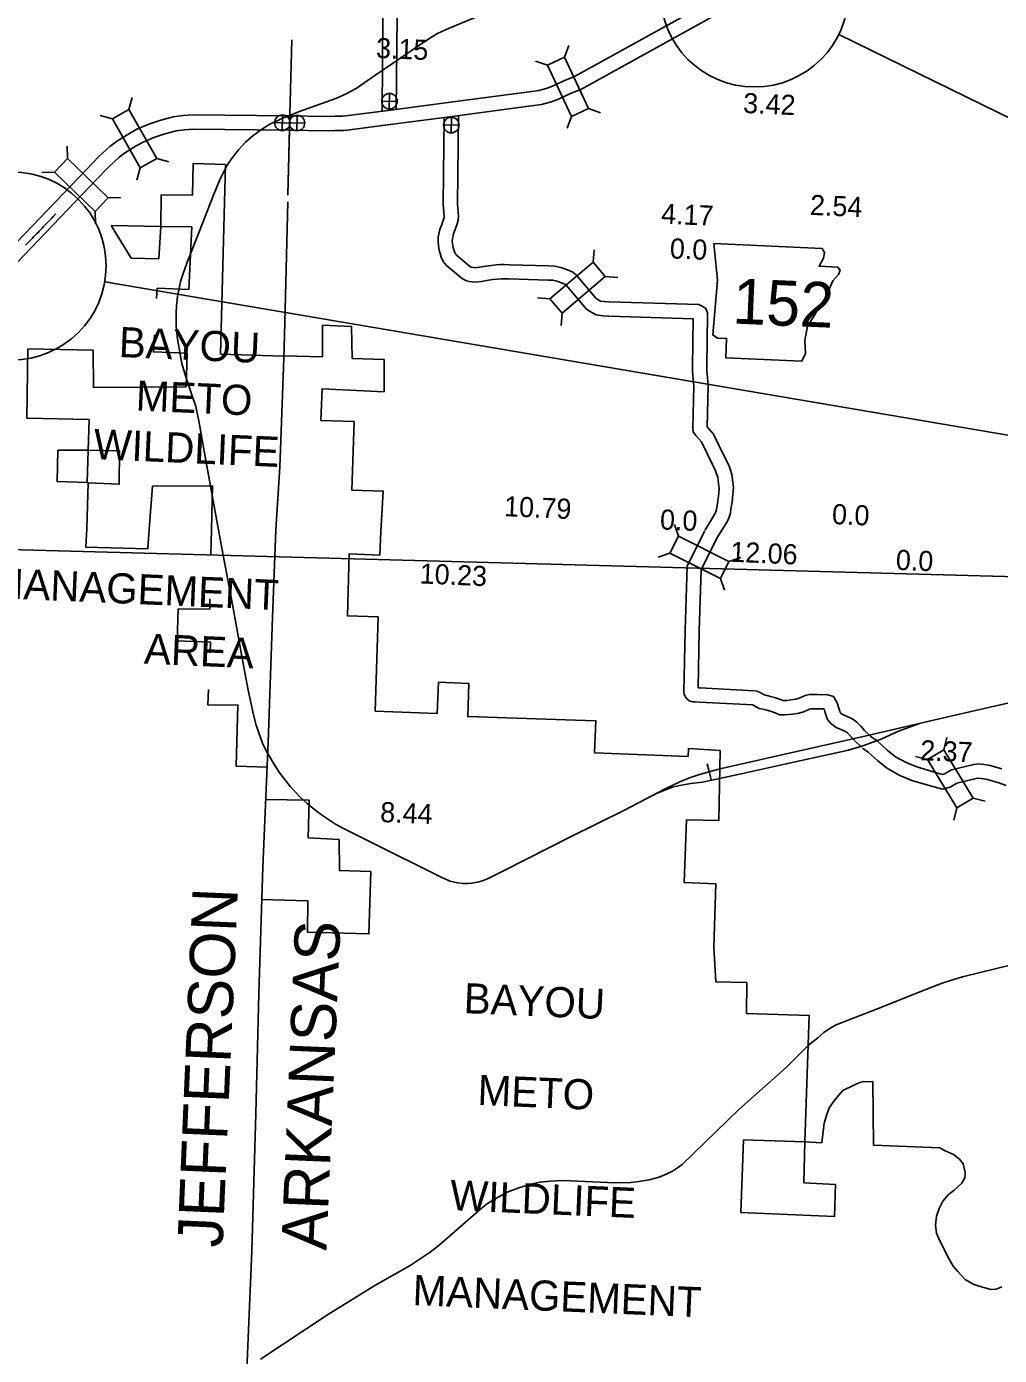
# Model space of a CAD drawing. Extents: x 1196286 to 1268366, y 2040822 to 2082115.
# Drawn here: x 1200093 to 1204184, y 2071244 to 2076830 of the extents above; entities that cross this region are included whole.
import ezdxf

# ---------------------------------------------------------------- set-up
doc = ezdxf.new("R2010")
doc.units = 0
for name, color, linetype in [('10', 7, 'Continuous'), ('55', 7, 'Continuous'), ('Level 100', 7, 'Continuous'), ('Level 70', 7, 'Continuous'), ('Level 78', 7, 'Continuous'), ('Level 8', 7, 'Continuous'), ('Level 82', 7, 'Continuous'), ('Level 84', 7, 'Continuous'), ('Level 87', 7, 'Continuous'), ('Level 95', 7, 'Continuous'), ('Level 96', 7, 'Continuous'), ('Level 97', 7, 'Continuous'), ('Level 98', 7, 'Continuous')]:
    doc.layers.add(name, color=color, linetype=linetype)

msp = doc.modelspace()

# ---------------------------------------------------------------- linework, layer by layer
at = {"layer": '10'}
for q in [(1202955.4, 2073731.2), (1202972, 2073665.2)]:
    msp.add_line((1202963.7, 2073698.2), q, dxfattribs=at)
for points in [[(1202150.4, 2076940.5), (1202116.4, 2076923.6), (1202008.7, 2076880), (1201857.3, 2076817.3), (1201821, 2076800.8), (1201785.3, 2076778.5), (1201558.1, 2076623.9), (1201479.7, 2076569.9), (1201437.3, 2076546.6), (1201393.2, 2076527.1), (1201236, 2076471.6), (1201170.7, 2076445.2), (1201116.4, 2076419.2), (1201080.8, 2076396.6)], [(1201080.8, 2076396.6), (1201044.5, 2076371), (1201013.9, 2076343.4), (1200984.8, 2076311.7), (1200954.9, 2076273.3), (1200937.3, 2076247.7), (1200922.1, 2076220.1), (1200904.1, 2076183.4), (1200878.9, 2076121.3), (1200806.6, 2075934.9), (1200771, 2075846.6), (1200752.7, 2075796.1), (1200741.2, 2075758.6), (1200734.3, 2075729), (1200728.6, 2075695), (1200724.4, 2075655.6), (1200722.1, 2075623.4), (1200722.5, 2075570.9), (1200727.8, 2075515.8), (1200746.2, 2075413.1), (1200761.9, 2075362.2), (1200788.6, 2075281.4), (1200805.1, 2075232.5), (1200818.1, 2075172), (1200836, 2075069.1), (1200875.4, 2074851.4), (1200919, 2074615.4), (1200959.6, 2074400.4), (1201000.5, 2074174.7), (1201025.7, 2074040.4), (1201047.1, 2073936.8), (1201058.8, 2073893.2), (1201069.5, 2073860.3), (1201086, 2073818.2), (1201101.3, 2073784.9), (1201139.5, 2073719.9), (1201157.9, 2073691.9), (1201203, 2073634.5), (1201243.9, 2073591.2), (1201274.9, 2073562.5), (1201310.8, 2073533.1), (1201337.6, 2073513.2), (1201362.8, 2073496.7), (1201391.9, 2073477.6), (1201428.2, 2073457), (1201540.6, 2073401.1), (1201839.2, 2073252.3), (1201874.8, 2073237.4), (1201905.7, 2073230.5), (1201926.4, 2073227.8), (1201948.2, 2073227.8), (1201966.1, 2073229), (1201988.7, 2073233.2), (1202010.5, 2073239.3), (1202034.6, 2073248.8), (1202100.7, 2073282.9), (1202380.6, 2073424.4), (1202607.7, 2073535.8), (1202780.9, 2073627.6), (1202840.6, 2073654.7), (1202880.7, 2073671.2), (1202913.6, 2073683.1), (1202961.4, 2073697.6), (1203014.9, 2073711), (1203325.4, 2073781.4), (1203635.9, 2073851.4), (1203870.2, 2073905.3), (1204137.1, 2073967.3), (1204305.7, 2074005.9)], [(1203846.9, 2073899.9), (1203759.2, 2073867.5), (1203688.6, 2073836.2), (1203614, 2073807.3), (1203548.9, 2073788.8), (1203286.4, 2073730.1), (1203098.5, 2073688.4), (1202987.7, 2073664.3), (1202935.5, 2073653.8), (1202886.6, 2073648.2), (1202839.2, 2073640.2), (1202809.5, 2073632.1), (1202738.3, 2073605)], [(1204451.5, 2072939), (1204028.9, 2072835.7), (1203977.5, 2072820), (1203943.1, 2072808.1), (1203906.2, 2072794.3), (1203834.8, 2072766.7), (1203692.1, 2072709.1), (1203497.4, 2072633.3), (1203471.7, 2072619.5), (1203445.4, 2072601.4), (1203419.7, 2072579.4), (1203381.5, 2072547.5), (1203286.4, 2072453.5), (1203088.5, 2072278.1), (1202849.4, 2072047), (1202830.6, 2072032), (1202808.7, 2072018.2), (1202783, 2072005.7), (1202753, 2071993.1), (1202711, 2071981.9), (1202667.8, 2071974.3), (1202634, 2071971.2), (1202567, 2071969.3), (1202349.2, 2071978.7), (1202295.3, 2071976.8), (1202250.9, 2071972.5), (1202215.2, 2071964.3), (1202162.6, 2071948.7), (1202114.4, 2071930.5), (1202075.6, 2071909.2), (1202031.1, 2071882.3), (1202003, 2071859.7), (1201827.7, 2071707.5), (1201790.1, 2071678), (1201705.6, 2071622.3), (1201557.8, 2071537.7), (1201362.5, 2071416.8), (1201077, 2071227.7)]]:
    msp.add_lwpolyline(points, dxfattribs=at)
at = {"layer": '55'}
for points in [[(1201208.7, 2076773.7), (1201199.8, 2076460.4), (1201191.6, 2076120.9)], [(1201208.7, 2076773.7), (1201199.8, 2076460.4), (1201199.7, 2076456)], [(1201198.2, 2076394.8), (1201191.6, 2076120.9)], [(1201191.4, 2076092.7), (1201179.2, 2075584), (1201175.2, 2075434.1), (1201158.1, 2074977.4), (1201141.4, 2074714.5)], [(1201191.4, 2076092.7), (1201179.2, 2075584), (1201175.2, 2075434.1), (1201158.1, 2074977.4), (1201141.4, 2074714.5)], [(1200995.4, 2070159.5), (1201003.9, 2070617.1), (1201018, 2071150.3), (1201039.9, 2071682.9), (1201057.3, 2072260.8), (1201069.7, 2072763.6), (1201086.6, 2073295.8), (1201108.5, 2073820.9), (1201126.8, 2074347), (1201141.4, 2074714.5)], [(1200995.4, 2070159.5), (1201003.9, 2070617.1), (1201018, 2071150.3), (1201039.9, 2071682.9), (1201057.3, 2072260.8), (1201069.7, 2072763.6), (1201086.6, 2073295.8), (1201108.5, 2073820.9), (1201126.8, 2074347), (1201141.4, 2074714.5)]]:
    msp.add_lwpolyline(points, dxfattribs=at)
at = {"layer": 'Level 100'}
for p, q in [((1201618.5, 2076483.4), (1201619.8, 2076548.5)), ((1201586.6, 2076516.6), (1201651.7, 2076515.3)), ((1201167.4, 2076392.9), (1201169.6, 2076457.9)), ((1201229.8, 2076391.9), (1201231.1, 2076457)), ((1201878.4, 2076383.2), (1201879.7, 2076448.3)), ((1201201, 2076424.3), (1201136, 2076426.5)), ((1201197.9, 2076425.1), (1201263, 2076423.8)), ((1201846.5, 2076416.4), (1201911.6, 2076415.1))]:
    msp.add_line(p, q, dxfattribs=at)
for centre, radius in [((1201619.1, 2076516), 32.6), ((1201168.5, 2076425.4), 32.5), ((1201230.5, 2076424.4), 32.6), ((1201879, 2076415.7), 32.6)]:
    msp.add_circle(centre, radius, dxfattribs=at)
at = {"layer": 'Level 70'}
for points in [[(1201171.9, 2075444.9), (1200909, 2075453.3), (1200929.5, 2076250), (1200794.2, 2076253.8), (1200791.4, 2076121.8), (1200659.9, 2076123.1), (1200657.5, 2075989.7), (1200649, 2075854.1), (1200533.5, 2075856.8), (1200449.6, 2075994.1)], [(1200449.6, 2075994.1), (1200657.5, 2075989.7), (1200787.8, 2075987.4), (1200775.3, 2075724.9), (1200642.5, 2075730.2), (1200640, 2075687.4)], [(1201582.5, 2074708), (1201593, 2074877), (1201460.4, 2074881.3), (1201471.2, 2075169.2), (1201331, 2075174.4), (1201335.9, 2075307.7), (1201596.4, 2075294.6), (1201596.3, 2075430.7), (1201462.7, 2075435.2), (1201459.2, 2075569.4), (1201338.2, 2075575.3), (1201337.5, 2075440.9), (1201173.8, 2075445.3)], [(1200631, 2075533.4), (1200626.9, 2075462.2), (1200768.3, 2075456.4), (1200764.1, 2075315.5), (1200375.1, 2075312.6), (1200373.8, 2075468.9), (1200099.3, 2075475), (1200093.9, 2075183.8), (1200356.5, 2075177.8), (1200352.8, 2075048.9), (1200225.4, 2075049.1), (1200221.4, 2074917), (1200347.6, 2074913.2), (1200352.3, 2074912.1), (1200346.3, 2074720.6)], [(1200347.6, 2074913.2), (1200352.8, 2075048.9)], [(1200352.8, 2075048.9), (1200484.3, 2075045.8), (1200483.1, 2074905.6), (1200352.3, 2074912.1)], [(1200609.4, 2074717.7), (1200623.3, 2074897.7), (1200874.7, 2074899.6), (1200870.3, 2074715.9)], [(1200609.4, 2074717.7), (1200602.8, 2074635), (1200342.2, 2074641.9), (1200346.3, 2074720.6)], [(1200870.3, 2074715.9), (1200868.1, 2074606.1)], [(1203361.2, 2071969.2), (1203364.8, 2072141.6), (1203383.9, 2072673.2), (1203120.1, 2072681.4), (1203121.2, 2072811), (1202991, 2072814.7), (1202983.5, 2072960.4), (1202990.7, 2073226.3), (1202858.4, 2073231.8), (1202867.4, 2073494.9), (1203003.8, 2073492.8), (1203009, 2073787.3), (1202875.9, 2073794.5), (1202874.7, 2073761.6), (1202481.2, 2073776.4), (1202486.8, 2073911.7), (1202359, 2073916.3), (1201948.2, 2073929), (1201952.8, 2074068), (1201825.6, 2074073.8), (1201819.6, 2073941.9), (1201559.7, 2073952.7), (1201571.9, 2074347.9), (1201442.7, 2074353.4), (1201449.2, 2074613.3), (1201578.8, 2074608.2), (1201582.5, 2074708)], [(1200864.5, 2074424.6), (1200863.6, 2074380.2), (1200731.2, 2074382), (1200727.1, 2074247.2), (1200866.7, 2074242.3), (1200864.9, 2074197.7)], [(1200858.4, 2074043.6), (1200855.7, 2073978.4), (1200982.2, 2073977.7), (1200974.7, 2073721.4), (1201106.5, 2073716.6)], [(1201080.1, 2073160.3), (1201275.3, 2073154.5), (1201274.3, 2073022.9), (1201532.7, 2073015.5), (1201540.5, 2073277.6), (1201408.5, 2073282.8), (1201407.5, 2073412.3), (1201277.9, 2073419.1), (1201280.9, 2073577.5), (1201096.4, 2073581.2)], [(1203364.8, 2072141.6), (1203436.7, 2072138.1), (1203443.2, 2072186.4), (1203446.2, 2072218.7), (1203455.2, 2072248), (1203467.7, 2072284.1), (1203491.3, 2072318.2), (1203525.8, 2072356.9), (1203569.4, 2072379), (1203597.2, 2072390.8), (1203613.6, 2072395.2)], [(1203613.6, 2072395.2), (1203627.5, 2072393.8), (1203652, 2072395.1), (1203653.9, 2072127.7), (1203932.8, 2072116.2), (1203949.5, 2072106.5), (1203967.9, 2072098.6), (1203990.8, 2072088.7), (1204015.4, 2072068.5), (1204030.8, 2072049.6), (1204040, 2072012.6), (1204038.6, 2071991), (1204024.9, 2071968.5), (1203992.5, 2071936.4), (1203969.4, 2071919.7), (1203945.6, 2071891.7), (1203930.8, 2071861.4), (1203919.6, 2071829.2), (1203914.7, 2071791.4), (1203918.8, 2071757.8), (1203933.3, 2071725), (1203948.8, 2071696.7), (1203964.8, 2071660.8), (1203989.4, 2071619.3), (1204008.7, 2071596.5), (1204040, 2071563.4), (1204072.7, 2071543.7), (1204098.1, 2071535.1), (1204148.1, 2071521.4), (1204170.2, 2071522.7), (1204194, 2071532.6)], [(1203364.8, 2072141.6), (1203107.8, 2072149.9), (1203095.8, 2071844.9), (1203490.5, 2071827.7), (1203494.4, 2071962.6), (1203361.2, 2071969.2)]]:
    msp.add_lwpolyline(points, dxfattribs=at)
at = {"layer": 'Level 78'}
msp.add_lwpolyline([(1202982.3, 2075917.3), (1202998.6, 2075764.2), (1202978.6, 2075533.9), (1202998.3, 2075520.4), (1203036.3, 2075518.7), (1203032.9, 2075437.6), (1203352.3, 2075423.9), (1203368.9, 2075456.2), (1203366.2, 2075509.7), (1203376.4, 2075570.2), (1203406.3, 2075617.2), (1203425.6, 2075651.9), (1203452.6, 2075688.9), (1203469.5, 2075728.8), (1203483.6, 2075761.2), (1203507.6, 2075788.1), (1203513.5, 2075805.6), (1203503.9, 2075818.8), (1203425.3, 2075822.1), (1203444.5, 2075856.9), (1203448, 2075879.6), (1203438.3, 2075897.5)], close=True, dxfattribs=at)
at = {"layer": 'Level 8'}
for p in [(1203508.5, 2076797.1), (1200422, 2075757.5), (1199280.2, 2074652.1)]:
    msp.add_line(p, (1208376.7, 2074405.8), dxfattribs=at)
msp.add_lwpolyline([(1200216.8, 2076042.6), (1200205.5, 2076031), (1200199.7, 2076025), (1200193.9, 2076019), (1200188, 2076013), (1200182.2, 2076007), (1200176.3, 2076001), (1200170.5, 2075995), (1200164.7, 2075989), (1200158.9, 2075983), (1200153.1, 2075977), (1200147.3, 2075970.9), (1200141.5, 2075964.9), (1200135.8, 2075958.9), (1200130, 2075952.9), (1200124.2, 2075946.9), (1200118.4, 2075940.9), (1200112.6, 2075934.9), (1200106.8, 2075928.9), (1200101, 2075922.9), (1200095.2, 2075916.9), (1200089.4, 2075910.9)], dxfattribs=at)
for centre in [(1203153.8, 2076971.3), (1200032.3, 2075823.8)]:
    msp.add_circle(centre, 395.3, dxfattribs=at)
at = {"layer": 'Level 84'}
for points in [[(1203647.6, 2077321.7), (1203469.2, 2077213.2), (1202397.6, 2076620.1), (1202358.9, 2076604.5), (1202331.8, 2076591.8), (1202297.8, 2076576.5), (1202278, 2076569.9), (1202246.6, 2076561.7), (1202206.6, 2076555.5), (1201875.5, 2076511.7), (1201613.8, 2076477.3), (1201433.8, 2076454.5), (1201422.2, 2076453.1), (1201405.9, 2076452.7), (1201391.5, 2076453), (1201353.5, 2076452.1), (1201200.1, 2076454.6)], [(1203678.7, 2077270.4), (1203499.3, 2077161.3), (1202423.5, 2076565.9), (1202382.9, 2076549.5), (1202356.9, 2076537.2), (1202319.6, 2076520.6), (1202295.1, 2076512.4), (1202258.8, 2076502.9), (1202215.1, 2076496.1), (1201883.3, 2076452.2), (1201621.5, 2076417.8), (1201441.1, 2076395), (1201426.6, 2076393.2), (1201406.2, 2076392.6), (1201391.5, 2076393), (1201353.7, 2076392.1), (1201197.9, 2076394.6), (1201197.6, 2076394.6)], [(1201060.3, 2076456.4), (1200792.8, 2076458.5), (1200752.2, 2076455.9), (1200709.6, 2076450.5), (1200658.1, 2076435.8), (1200607.9, 2076420.2), (1200557.2, 2076398.5), (1200523.9, 2076379.5), (1200471, 2076347.1), (1200443.8, 2076326.2), (1200397.6, 2076283), (1200344.7, 2076229.1), (1199855.1, 2075719.1)], [(1201199.2, 2076454.6), (1201198.8, 2076454.6), (1201060.5, 2076456.4)], [(1201059.8, 2076396.4), (1200794.4, 2076398.5), (1200757.9, 2076396.1), (1200721.7, 2076391.5), (1200675.3, 2076378.3), (1200628.7, 2076363.8), (1200583.9, 2076344.6), (1200554.5, 2076327.9), (1200505, 2076297.6), (1200482.7, 2076280.4), (1200439.5, 2076240.1), (1200387.8, 2076187.3), (1199898.4, 2075677.5)], [(1201197.8, 2076394.6), (1201059.7, 2076396.4)]]:
    msp.add_lwpolyline(points, dxfattribs=at)
at = {"layer": 'Level 87'}
for points in [[(1201595.6, 2077154.5), (1201593, 2077008.4), (1201591.5, 2076874.7), (1201587.9, 2076474)], [(1201655.7, 2077160.2), (1201653, 2077007.6), (1201651.5, 2076874.1), (1201647.9, 2076481.8)], [(1202977.3, 2074989.1), (1202990.3, 2074962.6), (1202994.7, 2074950.2), (1202999.1, 2074935.2), (1203001.1, 2074918.3), (1203004.7, 2074890), (1203002, 2074854.8), (1203001.4, 2074848)], [(1203028.3, 2075021.5), (1203045.7, 2074985.9), (1203051.8, 2074968.7), (1203058.1, 2074947.3), (1203060.7, 2074925.5), (1203065, 2074891.4), (1203061.8, 2074849.9), (1203061.2, 2074843)], [(1203001.6, 2074849.7), (1202999.2, 2074832.8), (1202995.4, 2074809.6), (1202994, 2074798.4), (1202990.9, 2074789.5), (1202986.2, 2074778.1), (1202945, 2074711.1)], [(1203061, 2074841.3), (1203058.5, 2074823.7), (1203054.8, 2074801), (1203052.8, 2074784.7), (1203047, 2074768.2), (1203039.9, 2074750.8), (1202996.1, 2074679.7)], [(1202943.7, 2074708.8), (1202870.3, 2074561.9), (1202861.7, 2074291.9), (1202856.2, 2074031.4)], [(1202997.4, 2074682), (1202929.9, 2074546.8), (1202921.7, 2074290.3), (1202916.6, 2074050.5)]]:
    msp.add_lwpolyline(points, dxfattribs=at)
at = {"layer": 'Level 95'}
for points in [[(1201849, 2076446.6), (1201846.7, 2076210.6), (1201845.6, 2076081.4), (1201849, 2076032.2), (1201848.7, 2076025.6), (1201846.9, 2076019.5), (1201838.9, 2075997.9), (1201830.5, 2075977.1), (1201823.8, 2075945), (1201823.4, 2075924.3), (1201825.1, 2075909.2), (1201828.7, 2075889.3), (1201831.8, 2075875.4), (1201836.7, 2075860.9), (1201844.6, 2075842.9), (1201858.3, 2075826), (1201917.3, 2075776.3), (1201929.5, 2075767.6), (1201943.4, 2075760.9), (1201953.9, 2075758.9), (1201966.4, 2075756.8), (1201979.9, 2075756), (1202005.8, 2075758.8), (1202035.1, 2075763.6), (1202053.8, 2075766.4), (1202073, 2075768.4), (1202089.2, 2075769.7), (1202099.9, 2075769.8), (1202121.2, 2075768.8), (1202286.4, 2075763.6), (1202305.8, 2075763.2), (1202322.6, 2075759.5), (1202346.1, 2075750.8), (1202358.6, 2075745.8), (1202361.4, 2075743.4), (1202447.3, 2075642.1), (1202469.4, 2075627.9), (1202488.6, 2075618), (1202516.5, 2075614.1), (1202540.8, 2075613), (1202895.8, 2075601.7), (1202893.2, 2075400.1), (1202893.7, 2075377), (1202895.1, 2075363.9), (1202898.7, 2075317.6), (1202895.1, 2075141), (1202896.4, 2075126.7), (1202907.5, 2075110.6), (1202931, 2075083.6), (1202977.3, 2074989.1)], [(1201909.1, 2076455.2), (1201906.7, 2076210), (1201905.6, 2076083.2), (1201909.1, 2076032.8), (1201908.2, 2076015.8), (1201904, 2076000.9), (1201894.9, 2075976.2), (1201888.1, 2075959.5), (1201883.7, 2075938.2), (1201883.4, 2075927), (1201884.5, 2075917.9), (1201887.5, 2075901.1), (1201889.7, 2075891.5), (1201892.7, 2075882.6), (1201896.3, 2075874.5), (1201901.3, 2075868.3), (1201954.2, 2075823.8), (1201960.3, 2075819.4), (1201962.5, 2075818.3), (1201964.6, 2075817.9), (1201973.1, 2075816.5), (1201978.4, 2075816.2), (1201997.7, 2075818.2), (1202025.7, 2075822.9), (1202046.3, 2075826), (1202067.5, 2075828.2), (1202086.5, 2075829.6), (1202100.9, 2075829.8), (1202123.5, 2075828.8), (1202287.9, 2075823.5), (1202312.8, 2075823.1), (1202339.5, 2075817.2), (1202367.6, 2075806.9), (1202390.5, 2075797.8), (1202404.3, 2075785.6), (1202487.3, 2075687.7), (1202499.5, 2075679.9), (1202507, 2075676), (1202521.9, 2075673.9), (1202543.1, 2075673), (1202919.2, 2075661), (1202930.7, 2075656), (1202936.7, 2075653), (1202948.9, 2075645.3), (1202955.7, 2075626.8), (1202956, 2075618.4), (1202953.2, 2075400.3), (1202953.6, 2075380.9), (1202954.9, 2075369.5), (1202958.7, 2075319.3), (1202955.3, 2075147.2), (1202981.4, 2075117), (1203028.3, 2075021.5)], [(1202916.6, 2074050.4), (1202925.5, 2074050), (1203151.9, 2074038)], [(1203155.8, 2074037.5), (1203163.7, 2074036), (1203178.2, 2074030.4), (1203195, 2074020.3), (1203201.8, 2074019), (1203220.8, 2074014.1), (1203238.3, 2074009.7), (1203263.2, 2074000.8), (1203273.2, 2073996.5), (1203279, 2073996.2), (1203291.5, 2073997.5), (1203306.8, 2073999.3), (1203327.8, 2074002.5), (1203342.2, 2074006.9), (1203366.6, 2074018.4), (1203384, 2074021.5), (1203399.4, 2074022.3), (1203418.9, 2074021.6), (1203433.5, 2074021.3), (1203456.7, 2074021.9), (1203486.5, 2074013.9), (1203501.4, 2073987.3), (1203506.9, 2073968.7), (1203512.3, 2073952.5), (1203514.3, 2073946.9), (1203516.9, 2073943.8), (1203526.5, 2073936.6), (1203537.8, 2073932), (1203567, 2073918.6), (1203584.5, 2073905.3), (1203600.5, 2073888.3), (1203616.7, 2073871), (1203645.2, 2073843)], [(1202862, 2074015.3), (1202858.7, 2074021.9), (1202857.1, 2074028.3), (1202856.2, 2074031.4)], [(1202862, 2074015.3), (1202865.6, 2074009.7), (1202870.4, 2074002.9)], [(1202870.4, 2074002.9), (1202872.2, 2074001.3), (1202877.8, 2073996.5), (1202888.2, 2073992.9), (1202897.2, 2073991), (1202902.9, 2073991.2)], [(1202902.9, 2073991.2), (1202905, 2073990.8), (1202922.7, 2073990.1), (1203148.8, 2073978)], [(1203144.9, 2073978.5), (1203147.3, 2073978.1), (1203151.7, 2073976.4), (1203173.2, 2073963.4), (1203188.6, 2073960.4), (1203206, 2073955.9), (1203220.9, 2073952.2), (1203241.3, 2073944.9), (1203259.2, 2073937.2), (1203280.4, 2073936), (1203298.2, 2073937.9), (1203314.9, 2073939.9), (1203341, 2073943.8), (1203363.9, 2073950.7), (1203385, 2073960.7), (1203390.9, 2073961.8), (1203399.8, 2073962.3), (1203417.2, 2073961.6), (1203433.7, 2073961.3), (1203446.4, 2073961.6), (1203449.7, 2073950.6), (1203455.6, 2073932.9), (1203461.4, 2073916.6), (1203475.4, 2073900), (1203496.6, 2073883.9), (1203514, 2073876.9), (1203535.9, 2073866.8), (1203544.2, 2073860.6), (1203556.8, 2073847.2), (1203573.8, 2073829.1), (1203603.1, 2073800.3)], [(1203640.7, 2073846.6), (1203669.4, 2073827.5), (1203711.7, 2073788.6), (1203746.6, 2073760.7), (1203791, 2073736.3), (1203835.9, 2073718), (1203905.7, 2073697.2), (1203944.4, 2073686), (1203953.2, 2073688.3), (1203981.8, 2073705.7), (1204075.6, 2073728.1), (1204097.7, 2073730.4), (1204139.7, 2073725.1), (1204194, 2073709.3)], [(1203607.5, 2073796.6), (1203632.2, 2073780.2), (1203672.6, 2073743), (1203713.2, 2073710.6), (1203765.1, 2073682), (1203815.9, 2073661.3), (1203888.8, 2073639.7), (1203943.7, 2073623.7), (1203977, 2073632.5), (1204004.9, 2073649.5), (1204085.8, 2073668.8), (1204097, 2073670), (1204127.4, 2073666.2), (1204176.3, 2073651.9), (1204212.3, 2073640.2)]]:
    msp.add_lwpolyline(points, dxfattribs=at)
at = {"layer": 'Level 98'}
for p, q in [((1202355.1, 2076700.8), (1202373, 2076750.5)), ((1202283.4, 2076667.1), (1202233.7, 2076685)), ((1200522.8, 2076481.1), (1200536.7, 2076532)), ((1200454, 2076441.9), (1200403, 2076455.8)), ((1202384.5, 2076452.1), (1202366.6, 2076402.4)), ((1202456.1, 2076485.8), (1202505.8, 2076467.9)), ((1200265.5, 2076274.7), (1200264.4, 2076327.5)), ((1200640.4, 2076274.6), (1200691.3, 2076260.7)), ((1200210.6, 2076217.6), (1200157.8, 2076216.5)), ((1200571.6, 2076235.4), (1200557.6, 2076184.5)), ((1200436.9, 2076110.2), (1200489.7, 2076111.3)), ((1200382, 2076053.1), (1200383.1, 2076000.3)), ((1202475.2, 2075839.3), (1202479.6, 2075891.9)), ((1202526.5, 2075778.9), (1202579.1, 2075774.5)), ((1202294, 2075685.6), (1202241.4, 2075689.9)), ((1202345.2, 2075625.2), (1202340.9, 2075572.6)), ((1202833.7, 2074687.2), (1202817, 2074737.2)), ((1202798.2, 2074616.3), (1202748.2, 2074599.6)), ((1203046.2, 2074580.9), (1203096.3, 2074597.6)), ((1203010.8, 2074510.1), (1203027.5, 2074460)), ((1203949.3, 2073789.8), (1203961.9, 2073841.1)), ((1203881.7, 2073748.7), (1203830.4, 2073761.3)), ((1204072.7, 2073586.8), (1204124, 2073574.2)), ((1204005, 2073545.7), (1203992.5, 2073494.4))]:
    msp.add_line(p, q, dxfattribs=at)
for points in [[(1202283.4, 2076667.1), (1202384.5, 2076452.1), (1202456.1, 2076485.8), (1202355.1, 2076700.8)], [(1200640.4, 2076274.6), (1200522.8, 2076481.1), (1200454, 2076441.9), (1200571.6, 2076235.4)], [(1200210.6, 2076217.6), (1200382, 2076053.1), (1200436.9, 2076110.2), (1200265.5, 2076274.7)], [(1202345.2, 2075625.2), (1202526.5, 2075778.9), (1202475.2, 2075839.3), (1202294, 2075685.6)], [(1203046.2, 2074580.9), (1202833.7, 2074687.2), (1202798.2, 2074616.3), (1203010.8, 2074510.1)], [(1204072.7, 2073586.8), (1203949.3, 2073789.8), (1203881.7, 2073748.7), (1204005, 2073545.7)]]:
    msp.add_lwpolyline(points, close=True, dxfattribs=at)

# ---------------------------------------------------------------- texts
at = {"layer": 'Level 70'}
for s, p in [('BAYOU', (1200479.6, 2075441)), ('METO', (1200551, 2075215.8)), ('WILDLIFE', (1200373.2, 2075011.9)), ('MANAGEMENT', (1199937.3, 2074428.8)), ('AREA', (1200585.6, 2074151.8)), ('BAYOU', (1201929.6, 2072682.8)), ('METO', (1201987.7, 2072296.8)), ('WILDLIFE', (1201871.8, 2071854.9)), ('MANAGEMENT', (1201714.6, 2071455.8))]:
    msp.add_text(s, height=126.72, rotation=357.548, dxfattribs=at).set_placement(p)
at = {"layer": 'Level 78'}
msp.add_text('152', height=190.08, rotation=357.548, dxfattribs=at).set_placement((1203059.5, 2075581.8))
at = {"layer": 'Level 82'}
for s, p in [('3.15', (1201561.3, 2076698.4)), ('3.42', (1203104.9, 2076466.9)), ('2.54', (1203385.9, 2076038.4)), ('10.79', (1202099.8, 2074771.7)), ('10.23', (1201744.9, 2074489.2)), ('2.37', (1203849.2, 2073746.2)), ('8.44', (1201578.9, 2073486.4))]:
    msp.add_text(s, height=84.48, rotation=357.548, dxfattribs=at).set_placement(p)
at = {"layer": 'Level 96'}
for s, p in [('JEFFERSON', (1200917.3, 2071695.4)), ('ARKANSAS', (1201354.1, 2071683.8))]:
    msp.add_text(s, height=190.08, rotation=87.548, dxfattribs=at).set_placement(p)
at = {"layer": 'Level 97'}
for s, p in [('4.17', (1202760.1, 2076001.7)), ('0.0', (1202796.7, 2075855.6)), ('0.0', (1203478.4, 2074738.8)), ('0.0', (1202755.2, 2074716.2)), ('12.06', (1203050.8, 2074580.4)), ('0.0', (1203746.9, 2074546.6))]:
    msp.add_text(s, height=84.48, rotation=357.548, dxfattribs=at).set_placement(p)

doc.saveas('drawing.dxf')
